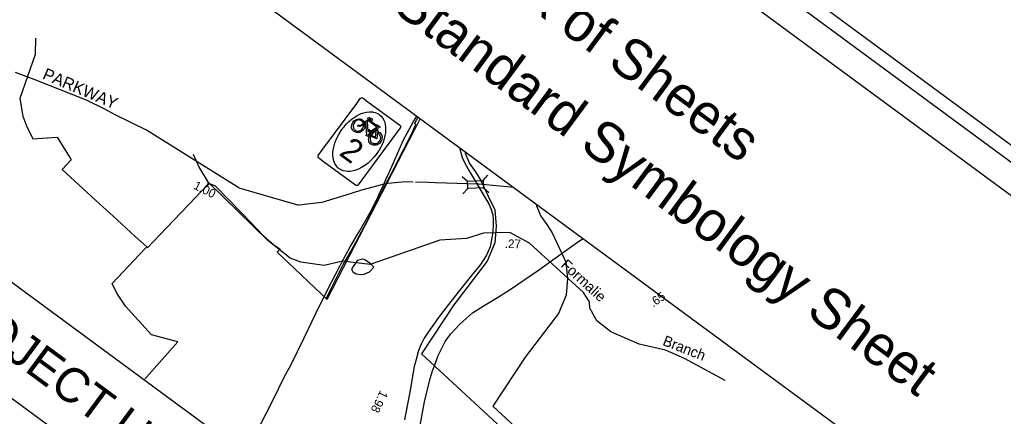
# Model space of a CAD drawing. Extents: x 945666 to 965748, y 644452 to 663300.
# Drawn here: x 953745 to 955579, y 660009 to 660750 of the extents above; entities that cross this region are included whole.
import ezdxf

# ---------------------------------------------------------------- set-up
doc = ezdxf.new("R2010")
doc.units = 0
for name, color, linetype in [('Exist Boundary Political City Limit New', 7, 'Continuous'), ('Exist Hydrographic Creek Single Shore', 7, 'Continuous'), ('Exist Hydrographic Lock CELL', 7, 'Continuous'), ('Exist Hydrographic Pond Under 1500 Sq Ft', 7, 'Continuous'), ('Exist Railroad Mainline', 7, 'Continuous'), ('Exist Road Blue Ridge Parkway', 7, 'Continuous'), ('Exist Road Blue Ridge Parkway Bike Route CELL', 7, 'Continuous'), ('Exist Road Blue Ridge Parkway Label', 7, 'Continuous'), ('Exist Road Primary Interstate Structure Federal Agency CELL', 7, 'Continuous'), ('Exist Road Primary US Mileage Hundredths English Label', 7, 'Continuous'), ('Exist Road Primary US UnDivided 4 Lane Attributed', 7, 'Continuous'), ('Exist Road Secondary Mileage Tenths English Label', 7, 'Continuous'), ('Old_Level_1', 7, 'Continuous'), ('Old_Level_28', 7, 'Continuous'), ('Old_Level_48', 7, 'Continuous'), ('Prop EOT', 7, 'Continuous'), ('Prop Paved Shoulder', 7, 'Continuous'), ('Sheet Plot Border Inside CELL', 7, 'Continuous'), ('Sheet Title CELL', 7, 'Continuous')]:
    doc.layers.add(name, color=color, linetype=linetype)

msp = doc.modelspace()

# ---------------------------------------------------------------- linework, layer by layer
at = {"layer": 'Exist Boundary Political City Limit New'}
msp.add_line((954082.7, 660428.2), (954098.8, 660443.6), dxfattribs=at)
for points in [[(953774.6, 660715.2), (953774, 660684.6), (953745.2, 660602.6), (953751.1, 660569.3), (953758.1, 660549.7), (953762.4, 660541.6), (953769.8, 660527.4), (953787.3, 660528.5), (953815, 660530.5), (953834, 660499.4), (953840.9, 660487.9), (953824.3, 660470), (953855.5, 660441.4), (953886.4, 660412.8), (953919, 660382.7), (953959.5, 660345.6), (953981.8, 660325.4)], [(954316.7, 660229.1), (954317.3, 660230.4), (954331.3, 660258.9), (954343.6, 660283.9), (954348.4, 660292.8), (954364.9, 660321.5), (954370.8, 660331.8), (954371.9, 660333.7), (954387, 660362.8), (954405, 660398.1), (954410.3, 660408.3), (954426.1, 660439.1), (954439.6, 660465.1), (954460.9, 660506.8), (954478.3, 660541.1), (954481, 660549.2), (954483.8, 660554.1), (954482, 660556.7), (954487.9, 660567.8)], [(954316.7, 660229.1), (954318, 660227.9), (954481.1, 660543.8), (954484.6, 660550.6), (954491.9, 660564.8)], [(954575.3, 660503.3), (954575.7, 660500.3), (954583.9, 660480.9), (954594.9, 660465.5), (954605, 660449.5), (954618.6, 660420.1), (954630.6, 660394.6), (954633.3, 660364.3), (954630.9, 660333.2), (954616.6, 660298.8), (954554.4, 660217.4), (954494.3, 660125.9), (954651.4, 659980)], [(953981.8, 660325.4), (953983.6, 660323.7), (954007.2, 660348.3), (954032.4, 660375), (954061.2, 660405.3), (954082.7, 660428.2)], [(953981.8, 660325.4), (953983.6, 660323.7), (954007.2, 660348.3), (954032.4, 660375), (954061.2, 660405.3), (954082.7, 660428.2)], [(954082.7, 660428.2), (954083.8, 660429.4), (954093.3, 660439.4), (954097.7, 660444.1), (954098, 660443.9), (954098.8, 660443.6)], [(954098.8, 660443.6), (954109.3, 660439.1), (954159.8, 660387.5), (954175.3, 660371.6), (954199.6, 660346.3), (954218.6, 660329.1), (954230.9, 660321.3), (954225, 660315.7), (954258.2, 660284.4), (954296, 660248.4), (954316.6, 660228.9), (954316.7, 660229.1)], [(954098.8, 660443.6), (954109.3, 660439.1), (954159.8, 660387.5), (954175.3, 660371.6), (954199.6, 660346.3), (954218.6, 660329.1), (954230.9, 660321.3), (954225, 660315.7), (954258.2, 660284.4), (954296, 660248.4), (954316.6, 660228.9), (954316.7, 660229.1)], [(953978.5, 660079.2), (953981.3, 660082.3), (954039.6, 660147.8), (953990.9, 660161.3), (953966.7, 660187.7), (953942.3, 660214.5), (953926, 660238.9), (953917.2, 660257), (953979, 660322.4), (953981.8, 660325.4)]]:
    msp.add_lwpolyline(points, dxfattribs=at)
at = {"layer": 'Exist Hydrographic Creek Single Shore'}
for points in [[(954097, 660445.6), (954079.2, 660475.4), (954069.3, 660497.9)], [(954249, 660304.5), (954207.5, 660337.5), (954097, 660445.6)], [(955060.2, 660076), (954984.8, 660116.8), (954948.9, 660132.5), (954899.9, 660143.9), (954847.4, 660166.6), (954821, 660187.4), (954808.2, 660211.2), (954807.7, 660222.9), (954796.5, 660240.1), (954695.8, 660332.6), (954658.7, 660352), (954609.5, 660351), (954578.2, 660341.2), (954528.6, 660338), (954398.4, 660292.4), (954346.8, 660298.8), (954312.9, 660290.9), (954269.1, 660296.7), (954249, 660304.5)]]:
    msp.add_lwpolyline(points, dxfattribs=at)
at = {"layer": 'Exist Hydrographic Lock CELL'}
for p, q in [((954364.8, 660285.3), (954375.3, 660300.9)), ((954364.9, 660281.3), (954364.8, 660285.3))]:
    msp.add_line(p, q, dxfattribs=at)
at = {"layer": 'Exist Hydrographic Pond Under 1500 Sq Ft'}
for points in [[(954375.3, 660300.9), (954384.4, 660303.3), (954389.7, 660301.1), (954398.5, 660294.7), (954405.3, 660287.7)], [(954364.9, 660281.3), (954366.2, 660278.6), (954372.5, 660274.9), (954379.9, 660273.7), (954387.2, 660274.6), (954397, 660279), (954405.3, 660287.7)]]:
    msp.add_lwpolyline(points, dxfattribs=at)
at = {"layer": 'Exist Railroad Mainline'}
msp.add_lwpolyline([(954565.4, 660510.6), (954565.8, 660508.4), (954570, 660492.5), (954575.4, 660480.2), (954585.3, 660463.3), (954598.6, 660441.3), (954609.4, 660423.5), (954619.7, 660405.6), (954623.2, 660397), (954627.1, 660385.2), (954628.1, 660376.9), (954627.9, 660364.1), (954626.8, 660349.3), (954624.3, 660335.5), (954621.9, 660325.5), (954615.4, 660310), (954604.1, 660292.7), (954587.3, 660271.7), (954565.2, 660243.9), (954548.8, 660223.6), (954533.8, 660204), (954525.8, 660193.8), (954516.9, 660180.8), (954506.9, 660166.2), (954499, 660155), (954493.3, 660143.7), (954488.6, 660131.9), (954484.1, 660115.3), (954480.7, 660102), (954477.5, 660084.1), (954473.5, 660061.1), (954468, 660031.6), (954462.2, 660002.7)], dxfattribs=at)
at = {"layer": 'Exist Road Blue Ridge Parkway'}
for p, q in [((954478.4, 660446.3), (954465.1, 660446.6)), ((954153.6, 660435.7), (954265.6, 660403.4))]:
    msp.add_line(p, q, dxfattribs=at)
for points in [[(953903.8, 660582.4), (953869.3, 660599.6), (953771.7, 660638.2), (953737.3, 660650.8)], [(954045.8, 660503.2), (953981.3, 660543.2), (953921.9, 660572.8), (953903.8, 660582.4)], [(954153.6, 660435.7), (954045.8, 660503.2)], [(954465.1, 660446.6), (954431.1, 660443.5), (954423.9, 660442.4)], [(954423.9, 660442.4), (954380.5, 660430.8), (954353.4, 660422.1)], [(954601, 660442.3), (954579.9, 660443.4), (954520.5, 660445.2), (954507.3, 660445.5), (954482.7, 660446.2)], [(954666.6, 660436), (954601, 660442.3)], [(954353.4, 660422.1), (954308.4, 660408.1), (954265.6, 660403.4)]]:
    msp.add_lwpolyline(points, dxfattribs=at)
at = {"layer": 'Exist Road Blue Ridge Parkway Bike Route CELL'}
for points in [[(954384.9, 660603.4), (954385.2, 660603.2), (954394.3, 660596.5), (954444.7, 660559.3), (954453.7, 660552.7), (954454, 660552.4), (954454.2, 660552.2), (954454.4, 660552), (954454.5, 660551.8), (954454.7, 660551.6), (954454.9, 660551.2), (954455, 660550.9), (954455.1, 660550.7), (954455.1, 660550.4), (954455.2, 660549.9), (954455.2, 660549.6), (954455.2, 660549.4), (954455.2, 660549.2), (954455.1, 660549), (954455.1, 660548.9), (954455.1, 660548.7), (954455, 660548.5), (954454.9, 660548.2), (954454.7, 660547.9), (954454.7, 660547.8), (954454.6, 660547.7), (954447.8, 660538.5), (954383, 660450.5), (954376.3, 660441.5), (954376, 660441.1), (954375.8, 660441), (954375.6, 660440.8), (954375.4, 660440.7), (954375.2, 660440.5), (954374.8, 660440.3), (954374.5, 660440.2), (954374.3, 660440.1), (954374, 660440), (954373.8, 660440), (954373.5, 660440), (954373.4, 660440), (954373.2, 660440), (954373, 660440), (954372.9, 660440), (954372.7, 660440), (954372.3, 660440.1), (954372.1, 660440.2), (954371.8, 660440.3), (954371.6, 660440.4), (954371.5, 660440.5), (954371.4, 660440.5), (954371.3, 660440.6), (954371.1, 660440.7), (954362.1, 660447.4), (954311.7, 660484.5), (954302.6, 660491.2), (954302.4, 660491.4), (954302.3, 660491.5), (954302.1, 660491.7), (954302, 660491.8), (954301.8, 660492.1), (954301.7, 660492.3), (954301.5, 660492.5), (954301.4, 660492.7), (954301.4, 660492.9), (954301.3, 660493.2), (954301.2, 660493.3), (954301.2, 660493.5), (954301.2, 660493.6), (954301.2, 660493.8), (954301.1, 660494), (954301.1, 660494.2), (954301.1, 660494.4), (954301.2, 660494.6), (954301.2, 660494.8), (954301.2, 660495), (954301.3, 660495.2), (954301.3, 660495.3), (954301.3, 660495.4), (954301.4, 660495.5), (954301.4, 660495.5), (954301.4, 660495.6), (954301.5, 660495.7), (954301.5, 660495.8), (954301.5, 660495.8), (954301.6, 660495.9), (954301.6, 660496), (954301.6, 660496.1), (954301.7, 660496.1), (954301.8, 660496.3), (954308.5, 660505.4), (954373.4, 660593.4), (954380.1, 660602.4), (954380.3, 660602.7), (954380.5, 660602.9), (954380.7, 660603.1), (954380.9, 660603.2), (954381.1, 660603.4), (954381.6, 660603.6), (954381.8, 660603.7), (954382, 660603.8), (954382.3, 660603.8), (954382.8, 660603.9), (954383.2, 660603.9), (954383.3, 660603.9), (954383.5, 660603.9), (954383.7, 660603.8), (954383.8, 660603.8), (954384, 660603.8), (954384.3, 660603.7), (954384.6, 660603.6), (954384.8, 660603.4)], [(954340.8, 660471.3), (954339.6, 660472.3), (954338.4, 660473.3), (954336.1, 660475.8), (954333.8, 660479.2), (954332.7, 660481.4), (954331.8, 660483.3), (954331, 660485.5), (954330, 660488.8), (954329.1, 660495.4), (954329, 660503), (954330.5, 660511.8), (954332.4, 660519.2), (954335.1, 660525.9), (954339.8, 660535.5), (954344.2, 660542.6), (954346.6, 660545.9), (954348.4, 660548.2), (954349.8, 660549.9), (954351.8, 660552.3), (954355.1, 660555.9), (954358.8, 660559.4), (954361.3, 660561.6), (954362.7, 660562.8), (954365.4, 660564.9), (954367.8, 660566.7), (954374.1, 660570.7), (954380.6, 660573.8), (954386.7, 660575.9), (954391.7, 660577.2), (954397.1, 660577.8), (954400.7, 660577.7), (954402.6, 660577.5), (954404.6, 660577.2), (954407.7, 660576.6), (954411.1, 660575.2), (954414, 660573.7), (954416.1, 660572.2), (954418.9, 660569.7), (954421.4, 660566.5), (954423.8, 660562.3), (954425.5, 660558.1), (954426.5, 660553.9), (954427.2, 660548.7), (954427.3, 660543.8), (954426.9, 660538.3), (954426.1, 660533.1), (954424.5, 660526.9), (954422.4, 660520.8), (954420, 660515.3), (954417.5, 660510.1), (954415, 660505.8), (954413.5, 660503.5), (954409.9, 660498.1), (954405.5, 660492.7), (954400, 660486.7), (954394.6, 660481.9), (954388.8, 660477.4), (954382.5, 660473.4), (954376.5, 660470.4), (954371.5, 660468.5), (954366.7, 660467.2), (954361.2, 660466.2), (954356.7, 660466.1), (954352.3, 660466.5), (954348.2, 660467.5), (954345.8, 660468.4), (954344.6, 660469.1), (954343.5, 660469.6), (954342.4, 660470.3)], [(954410, 660553.9), (954417.2, 660549.8), (954417.3, 660548.9), (954416.1, 660548.1), (954414.1, 660548.9), (954413, 660548.3), (954412.4, 660541.5), (954416.5, 660538.8), (954419.4, 660535.4), (954420.8, 660530.7), (954420.5, 660527.3), (954420.3, 660525.5), (954419.2, 660523), (954417.7, 660520.7), (954415.6, 660518.5), (954413.8, 660517.1), (954411.4, 660516), (954409.4, 660515.3), (954406.5, 660515.1), (954404.1, 660515.4), (954401.3, 660516.5), (954399.8, 660517.5), (954397.2, 660520.2), (954396, 660522.5), (954395.7, 660524), (954395.6, 660526.8), (954395.9, 660529.2), (954397.1, 660533.5), (954398, 660535.3), (954398.9, 660532.4), (954398.5, 660528.5), (954398.3, 660525.8), (954399, 660523.7), (954400.6, 660521.1), (954402.2, 660519.8), (954404.8, 660518.7), (954407.8, 660518.3), (954410.3, 660518.7), (954413, 660519.8), (954415.4, 660522.2), (954417, 660524.5), (954417.8, 660526.7), (954418.1, 660529.1), (954418, 660531), (954417.3, 660533.5), (954416.1, 660535.1), (954413.9, 660537.5), (954412.2, 660539), (954411, 660527.4), (954398.9, 660532.4), (954398, 660535.3), (954408.6, 660530.1), (954409.7, 660539.7), (954404.8, 660538.8), (954400.3, 660534.2), (954398, 660535.3), (954399.7, 660537.4), (954402.9, 660540), (954406.1, 660541.1), (954410, 660542), (954410.8, 660545.9), (954395.9, 660536.5), (954398, 660535.3), (954397.1, 660533.5), (954394.6, 660534.9), (954394, 660533.1), (954394.8, 660531.4), (954390.8, 660533.1), (954390.7, 660534.8), (954392.5, 660534.6), (954390.5, 660557.7), (954389.1, 660556.7), (954389.1, 660553.1), (954388.6, 660550.1), (954387.7, 660547.2), (954386.5, 660544.8), (954384.8, 660542.9), (954382.2, 660540.7), (954379.1, 660539.2), (954375.8, 660538.7), (954372.7, 660539), (954369.6, 660540.3), (954367.6, 660541.6), (954365.8, 660543.2), (954363.9, 660547.8), (954363.7, 660549.9), (954364.3, 660553.9), (954366.2, 660557.9), (954368.1, 660560.5), (954370.3, 660562.3), (954372.8, 660563.5), (954375, 660564.2), (954377.9, 660564.6), (954380.1, 660564.4), (954382.4, 660563.6), (954384.4, 660562.3), (954388.3, 660558.8), (954387.6, 660555.8), (954382.5, 660551.6), (954378.8, 660550), (954375.5, 660550.7), (954375.3, 660552.4), (954382.1, 660553.5), (954385.8, 660556.6), (954385.2, 660557.7), (954383.9, 660559.4), (954381.3, 660561.4), (954379.5, 660562.1), (954376.6, 660562.4), (954372.7, 660561.3), (954369.9, 660559.2), (954368.1, 660556), (954366.8, 660552.7), (954366.5, 660550.3), (954367.1, 660548.2), (954368.2, 660545.5), (954369.7, 660543.8), (954372, 660542.3), (954374.9, 660541.7), (954378.1, 660542.2), (954380.9, 660543.6), (954382.8, 660544.6), (954384.4, 660546.5), (954385.7, 660548.9), (954386.6, 660552.2), (954388.3, 660558.8), (954394.8, 660563.2), (954395.1, 660560.5), (954392.6, 660558.8), (954394.3, 660540.6), (954395.1, 660542.2), (954395.3, 660544.7), (954396.1, 660544.8), (954398.9, 660542.7), (954396.9, 660541.1), (954396.1, 660539.5), (954410.9, 660548.7), (954395.1, 660560.5), (954394.8, 660563.2), (954394.4, 660566.5), (954397.4, 660567.2), (954402, 660564.6), (954402.7, 660562.1), (954400.9, 660561.6), (954398.5, 660563.7), (954396.5, 660564.6), (954396.6, 660564), (954397.5, 660563.3), (954396.5, 660562.7), (954412.6, 660550.6), (954413, 660550.9)]]:
    msp.add_lwpolyline(points, close=True, dxfattribs=at)
at = {"layer": 'Exist Road Primary Interstate Structure Federal Agency CELL'}
for p, q in [((954569.9, 660456.9), (954579.8, 660447.9)), ((954609, 660449.3), (954618, 660459.2)), ((954571.5, 660424.4), (954580.4, 660434.3)), ((954609.7, 660435.9), (954619.6, 660427))]:
    msp.add_line(p, q, dxfattribs=at)
msp.add_lwpolyline([(954579.8, 660447.9), (954609, 660449.3), (954609.7, 660435.7), (954580.4, 660434.3)], close=True, dxfattribs=at)
at = {"layer": 'Exist Road Primary US UnDivided 4 Lane Attributed'}
for points in [[(954423.9, 660442.4), (954424.9, 660444.8), (954427.7, 660451.2), (954433.7, 660464.4), (954439.1, 660475.3), (954448.4, 660496.8), (954459.9, 660523.9), (954479, 660559.5), (954485.3, 660569.7)], [(954166.2, 659936.9), (954173.7, 659953.1), (954191.2, 659988.5), (954204, 660013.2), (954216.1, 660037.2), (954238.6, 660083.2), (954250.3, 660104.8), (954275.3, 660155.8), (954297.1, 660200.8), (954318.9, 660245.2), (954342, 660289.2), (954345.3, 660295.9), (954361.3, 660325.8), (954378.4, 660355), (954388.6, 660372), (954399, 660390.8), (954411.5, 660415), (954416.6, 660426.8), (954422.4, 660438.5), (954423.9, 660442.4)], [(954489.3, 659978.7), (954499.9, 660036.2), (954510.2, 660079.5), (954514.6, 660093.8), (954518.4, 660103.1), (954525, 660122.3), (954538.1, 660148.7), (954548.7, 660163.2), (954565, 660180.7), (954578.1, 660192), (954589.5, 660202.3), (954614.3, 660217.9), (954636, 660230.7), (954657.9, 660244.3), (954710.3, 660280.4), (954785.2, 660334), (954795.3, 660341.1)]]:
    msp.add_lwpolyline(points, dxfattribs=at)
at = {"layer": 'Old_Level_1'}
msp.add_lwpolyline([(953667.4, 661172.9), (956829.7, 658840.6), (955088.6, 656479.8), (951926.2, 658812.1)], close=True, dxfattribs=at)
at = {"layer": 'Old_Level_28'}
msp.add_lwpolyline([(954708.2, 660405.3), (954708.6, 660402.3), (954716.8, 660382.9), (954727.8, 660367.4), (954737.9, 660351.5), (954751.5, 660322.1), (954763.5, 660296.6), (954766.2, 660266.3), (954763.9, 660235.2), (954749.5, 660200.8), (954687.3, 660119.4), (954627.2, 660027.9), (954784.3, 659882)], dxfattribs=at)
at = {"layer": 'Prop EOT'}
msp.add_lwpolyline([(954233.6, 659887.2), (953266.5, 660600.4), (953163.3, 660460.5), (954130.3, 659747.3)], close=True, dxfattribs=at)
at = {"layer": 'Sheet Plot Border Inside CELL'}
msp.add_lwpolyline([(945903.9, 654551), (959315.9, 644659.5), (965578.4, 653150.9), (952166.4, 663042.4)], close=True, dxfattribs=at)
at = {"layer": 'Sheet Title CELL'}
for points in [[(965382.3, 653263.9), (953471.1, 662048.6)], [(965312.3, 653253.4), (953884.2, 661681.7)]]:
    msp.add_lwpolyline(points, dxfattribs=at)

# ---------------------------------------------------------------- texts
at = {"layer": 'Exist Road Blue Ridge Parkway Bike Route CELL'}
msp.add_text('2', height=43.5, rotation=323.5908, dxfattribs=at).set_placement((954338.7, 660498.2))
at = {"layer": 'Exist Road Blue Ridge Parkway Label'}
msp.add_text('PARKWAY', height=22.08, rotation=336.8829, dxfattribs=at).set_placement((953786, 660640))
at = {"layer": 'Exist Road Primary US Mileage Hundredths English Label'}
for s, rotation, p in [('.65', 34.8961, (954926.2, 660212)), ('1.98', 243.8869, (954417.7, 660058.7))]:
    msp.add_text(s, height=16.24, rotation=rotation, dxfattribs=at).set_placement(p)
at = {"layer": 'Exist Road Secondary Mileage Tenths English Label'}
for s, rotation, p in [('1.00', 333.5089, (954067.5, 660434.7)), ('.27', 359.346, (954649.4, 660323.2))]:
    msp.add_text(s, height=16.24, rotation=rotation, dxfattribs=at).set_placement(p)
at = {"layer": 'Old_Level_48'}
msp.add_text('BEGIN TIP PROJECT U-5834', height=64.231, rotation=323.5908, dxfattribs=at).set_placement((953206.5, 660497))
at = {"layer": 'Prop Paved Shoulder'}
for s, rotation, p in [('Formalie', 317.4845, (954752.6, 660289.6)), ('Branch', 338.5773, (954942.3, 660142.5))]:
    msp.add_text(s, height=19.49, rotation=rotation, dxfattribs=at).set_placement(p)
at = {"layer": 'Sheet Title CELL'}
for s, p in [('See Sheet 1A For Index of Sheets', (953864.9, 661383.5)), ('See Sheet 1B For Standard Symbology Sheet', (953772.8, 661258.6))]:
    msp.add_text(s, height=75, rotation=323.5908, dxfattribs=at).set_placement(p)

doc.saveas('drawing.dxf')
